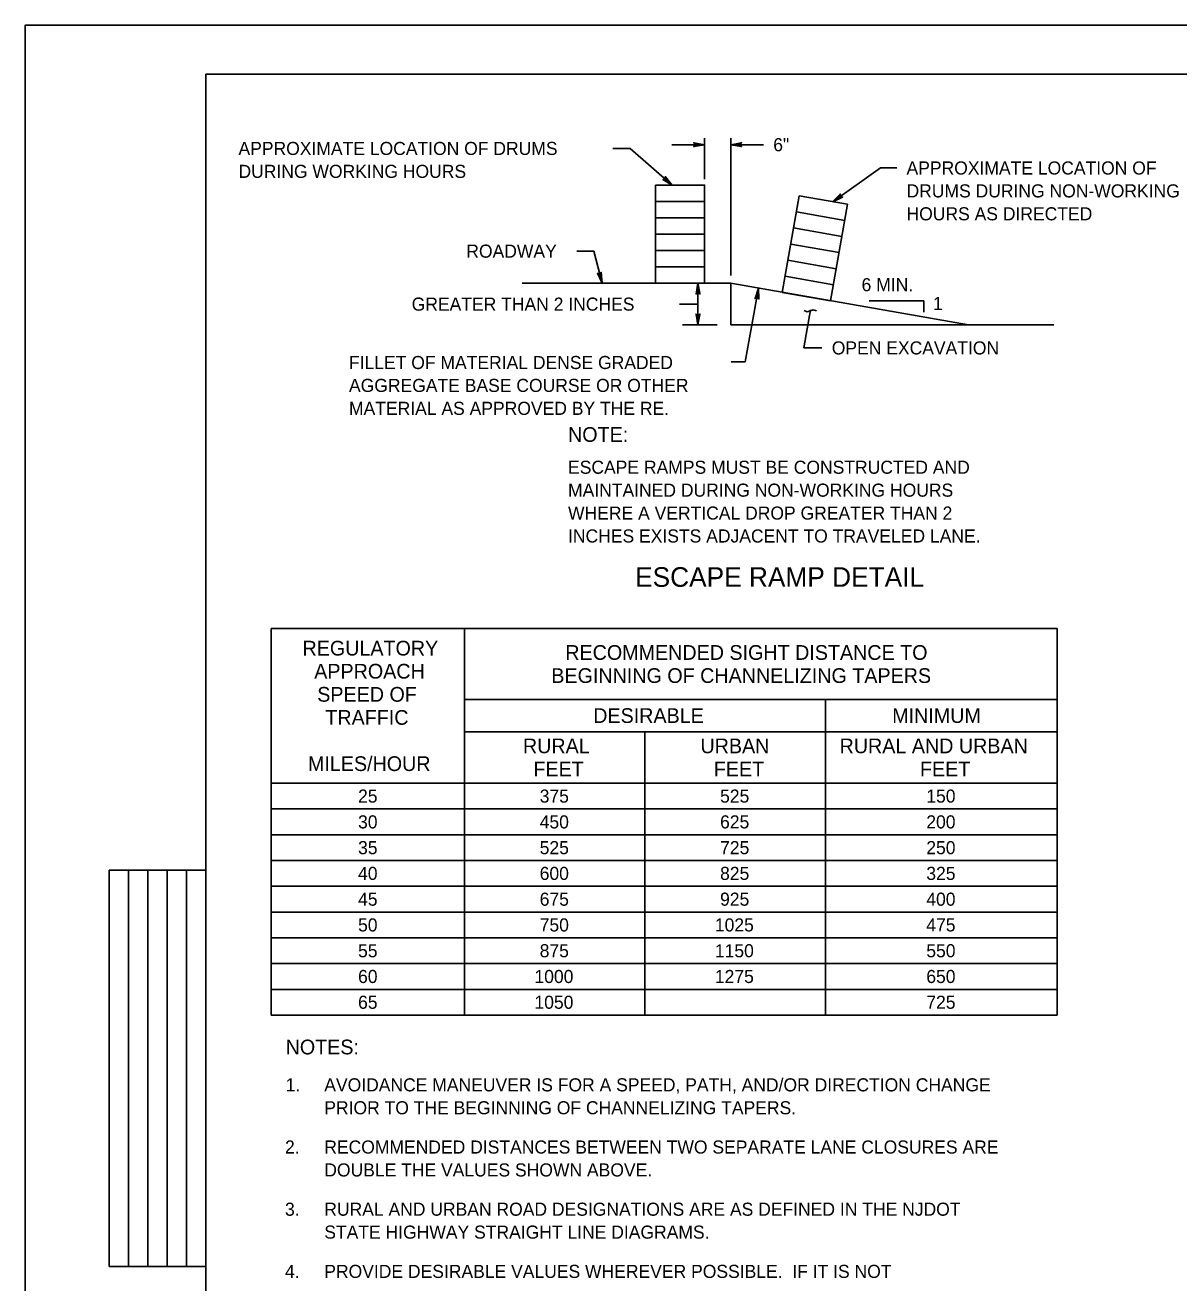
# Model space of a CAD drawing. Extents: x 499909 to 500993, y 502505 to 503165.
# Drawn here: x 499944.8 to 500297.3, y 502780.7 to 503165 of the extents above; entities that cross this region are included whole.
import ezdxf

# ---------------------------------------------------------------- set-up
doc = ezdxf.new("R2010")
doc.units = 0
for name, color, linetype in [('1', 7, 'Continuous'), ('24', 7, 'Continuous'), ('3', 7, 'Continuous'), ('39', 7, 'Continuous'), ('41', 7, 'Continuous'), ('5', 7, 'Continuous'), ('60', 7, 'Continuous')]:
    doc.layers.add(name, color=color, linetype=linetype)

msp = doc.modelspace()

# ---------------------------------------------------------------- linework, layer by layer
at = {"layer": '1'}
for p, q in [((500993, 503165), (499944.83, 503165)), ((500000, 503150), (500000, 502520)), ((500990, 503150), (500000, 503150)), ((499970.47, 502785.75), (499970.47, 502906.81)), ((499970.47, 502906.81), (500000, 502906.81)), ((499976.38, 502785.75), (499976.38, 502906.81)), ((499982.28, 502785.75), (499982.28, 502906.81)), ((499988.19, 502785.75), (499988.19, 502906.81)), ((499994.09, 502785.75), (499994.09, 502906.81)), ((500000, 502785.75), (499970.47, 502785.75))]:
    msp.add_line(p, q, dxfattribs=at)
at = {"layer": '24'}
for points in [[(500152.38, 503128.47), (500149.06, 503129.05), (500149.85, 503128.47), (500149.07, 503127.89), (500152.38, 503128.47), (500152.16, 503128.46), (500149.15, 503129.01), (500149.91, 503128.46), (500149.21, 503127.93), (500152.04, 503128.45), (500151.93, 503128.47), (500149.35, 503128.93), (500149.93, 503128.46), (500149.33, 503128.01), (500151.88, 503128.47), (500151.77, 503128.45), (500149.51, 503128.86), (500149.95, 503128.47), (500149.5, 503128.06), (500151.45, 503128.45), (500151.26, 503128.45), (500149.68, 503128.77), (500149.99, 503128.48), (500149.66, 503128.15), (500151.23, 503128.47), (500151.05, 503128.48), (500149.86, 503128.68), (500150.09, 503128.45), (500149.84, 503128.22), (500150.89, 503128.47), (500150.72, 503128.48), (500150.01, 503128.62), (500150.12, 503128.46), (500149.93, 503128.28), (500150.63, 503128.47), (500150.17, 503128.58), (500150.23, 503128.45), (500150.03, 503128.32), (500150.51, 503128.45), (500150.21, 503128.53), (500150.34, 503128.43), (500150.19, 503128.37), (500150.34, 503128.46), (500150.26, 503128.48)], [(500160.37, 503128.47), (500163.7, 503127.88), (500162.9, 503128.47), (500163.68, 503129.05), (500160.37, 503128.47), (500160.59, 503128.47), (500163.6, 503127.92), (500162.84, 503128.47), (500163.55, 503129), (500160.71, 503128.48), (500160.82, 503128.47), (500163.4, 503128.01), (500162.82, 503128.47), (500163.42, 503128.93), (500160.87, 503128.47), (500160.98, 503128.48), (500163.24, 503128.08), (500162.8, 503128.47), (500163.25, 503128.87), (500161.31, 503128.48), (500161.49, 503128.48), (500163.07, 503128.16), (500162.76, 503128.46), (500163.1, 503128.79), (500161.53, 503128.47), (500161.7, 503128.46), (500162.89, 503128.25), (500162.66, 503128.48), (500162.91, 503128.71), (500161.87, 503128.47), (500162.04, 503128.45), (500162.75, 503128.31), (500162.63, 503128.47), (500162.82, 503128.65), (500162.12, 503128.47), (500162.59, 503128.36), (500162.52, 503128.48), (500162.72, 503128.61), (500162.24, 503128.48), (500162.54, 503128.41), (500162.42, 503128.51), (500162.56, 503128.57), (500162.42, 503128.47), (500162.49, 503128.46)], [(500142.51, 503116.11), (500140.4, 503118.74), (500140.61, 503117.78), (500139.64, 503117.85), (500142.51, 503116.11), (500142.34, 503116.25), (500140.44, 503118.65), (500140.65, 503117.73), (500139.77, 503117.8), (500142.24, 503116.32), (500142.17, 503116.41), (500140.53, 503118.45), (500140.66, 503117.72), (500139.92, 503117.77), (500142.13, 503116.44), (500142.04, 503116.5), (500140.61, 503118.29), (500140.68, 503117.71), (500140.08, 503117.7), (500141.8, 503116.71), (500141.66, 503116.84), (500140.68, 503118.12), (500140.72, 503117.69), (500140.25, 503117.66), (500141.64, 503116.87), (500141.51, 503116.99), (500140.76, 503117.93), (500140.78, 503117.61), (500140.44, 503117.6), (500141.38, 503117.09), (500141.27, 503117.22), (500140.82, 503117.79), (500140.81, 503117.59), (500140.54, 503117.59), (500141.19, 503117.26), (500140.92, 503117.65), (500140.88, 503117.51), (500140.65, 503117.55), (500141.09, 503117.33), (500140.92, 503117.58), (500140.95, 503117.42), (500140.8, 503117.48), (500140.97, 503117.45), (500140.92, 503117.51)], [(500191.56, 503111.06), (500194.57, 503112.49), (500193.59, 503112.51), (500193.89, 503113.41), (500191.56, 503111.06), (500191.73, 503111.19), (500194.47, 503112.47), (500193.54, 503112.48), (500193.81, 503113.3), (500191.82, 503111.27), (500191.92, 503111.32), (500194.25, 503112.42), (500193.53, 503112.47), (500193.75, 503113.17), (500191.96, 503111.35), (500192.04, 503111.43), (500194.08, 503112.38), (500193.51, 503112.45), (500193.64, 503113.03), (500192.3, 503111.61), (500192.45, 503111.72), (500193.9, 503112.36), (500193.49, 503112.42), (500193.56, 503112.87), (500192.49, 503111.72), (500192.64, 503111.81), (500193.7, 503112.33), (500193.39, 503112.38), (500193.46, 503112.71), (500192.76, 503111.92), (500192.9, 503112), (500193.55, 503112.29), (500193.37, 503112.36), (500193.42, 503112.61), (500192.96, 503112.06), (500193.4, 503112.24), (500193.27, 503112.3), (500193.37, 503112.52), (500193.05, 503112.14), (500193.34, 503112.25), (500193.18, 503112.26), (500193.26, 503112.39), (500193.2, 503112.23), (500193.27, 503112.26)], [(500121.12, 503086.13), (500120.85, 503089.5), (500120.48, 503088.58), (500119.73, 503089.19), (500121.12, 503086.13), (500121.06, 503086.34), (500120.83, 503089.4), (500120.49, 503088.52), (500119.81, 503089.07), (500121.02, 503086.46), (500121.01, 503086.57), (500120.8, 503089.18), (500120.5, 503088.5), (500119.91, 503088.97), (500120.99, 503086.62), (500120.95, 503086.72), (500120.78, 503089), (500120.51, 503088.48), (500120, 503088.81), (500120.87, 503087.03), (500120.82, 503087.21), (500120.74, 503088.82), (500120.53, 503088.45), (500120.12, 503088.69), (500120.83, 503087.25), (500120.79, 503087.42), (500120.69, 503088.62), (500120.53, 503088.34), (500120.25, 503088.53), (500120.74, 503087.58), (500120.72, 503087.75), (500120.67, 503088.47), (500120.54, 503088.31), (500120.32, 503088.46), (500120.68, 503087.82), (500120.67, 503088.3), (500120.56, 503088.21), (500120.39, 503088.37), (500120.63, 503087.93), (500120.63, 503088.25), (500120.57, 503088.1), (500120.47, 503088.23), (500120.6, 503088.11), (500120.6, 503088.19)], [(500150.38, 503086.13), (500149.79, 503082.81), (500150.38, 503083.6), (500150.96, 503082.83), (500150.38, 503086.13), (500150.39, 503085.91), (500149.84, 503082.9), (500150.39, 503083.66), (500150.91, 503082.96), (500150.4, 503085.79), (500150.38, 503085.68), (500149.92, 503083.1), (500150.39, 503083.68), (500150.84, 503083.09), (500150.38, 503085.63), (500150.4, 503085.52), (500149.99, 503083.27), (500150.38, 503083.7), (500150.79, 503083.26), (500150.4, 503085.2), (500150.4, 503085.01), (500150.07, 503083.43), (500150.37, 503083.74), (500150.7, 503083.41), (500150.38, 503084.98), (500150.37, 503084.8), (500150.17, 503083.61), (500150.4, 503083.84), (500150.63, 503083.6), (500150.38, 503084.64), (500150.36, 503084.47), (500150.23, 503083.76), (500150.39, 503083.88), (500150.57, 503083.68), (500150.38, 503084.38), (500150.27, 503083.92), (500150.4, 503083.99), (500150.52, 503083.78), (500150.4, 503084.27), (500150.32, 503083.96), (500150.42, 503084.09), (500150.48, 503083.94), (500150.39, 503084.09), (500150.37, 503084.01)], [(500168.86, 503084.65), (500167.82, 503081.43), (500168.51, 503082.14), (500168.97, 503081.29), (500168.86, 503084.65), (500168.83, 503084.43), (500167.87, 503081.52), (500168.52, 503082.2), (500168.95, 503081.43), (500168.83, 503084.31), (500168.79, 503084.2), (500167.99, 503081.71), (500168.53, 503082.22), (500168.89, 503081.57), (500168.79, 503084.15), (500168.79, 503084.04), (500168.08, 503081.86), (500168.52, 503082.24), (500168.86, 503081.74), (500168.74, 503083.72), (500168.72, 503083.53), (500168.18, 503082.01), (500168.52, 503082.28), (500168.8, 503081.9), (500168.7, 503083.5), (500168.66, 503083.33), (500168.3, 503082.18), (500168.56, 503082.38), (500168.75, 503082.1), (500168.65, 503083.17), (500168.61, 503083), (500168.38, 503082.31), (500168.55, 503082.41), (500168.7, 503082.19), (500168.62, 503082.91), (500168.44, 503082.47), (500168.58, 503082.52), (500168.68, 503082.3), (500168.62, 503082.8), (500168.5, 503082.5), (500168.62, 503082.62), (500168.66, 503082.46), (500168.58, 503082.62), (500168.56, 503082.55)], [(500150.38, 503073.39), (500150.97, 503076.72), (500150.38, 503075.92), (500149.8, 503076.7), (500150.38, 503073.39), (500150.38, 503073.61), (500150.92, 503076.62), (500150.37, 503075.86), (500149.85, 503076.56), (500150.36, 503073.73), (500150.38, 503073.84), (500150.84, 503076.42), (500150.37, 503075.84), (500149.92, 503076.44), (500150.38, 503073.89), (500150.36, 503074), (500150.77, 503076.26), (500150.38, 503075.82), (500149.98, 503076.27), (500150.36, 503074.32), (500150.36, 503074.51), (500150.69, 503076.09), (500150.39, 503075.78), (500150.06, 503076.11), (500150.38, 503074.55), (500150.39, 503074.72), (500150.59, 503075.91), (500150.36, 503075.68), (500150.14, 503075.93), (500150.38, 503074.89), (500150.4, 503075.05), (500150.53, 503075.77), (500150.37, 503075.65), (500150.2, 503075.84), (500150.38, 503075.14), (500150.49, 503075.61), (500150.36, 503075.54), (500150.24, 503075.74), (500150.36, 503075.26), (500150.44, 503075.56), (500150.34, 503075.43), (500150.28, 503075.58), (500150.37, 503075.44), (500150.39, 503075.51)]]:
    msp.add_lwpolyline(points, dxfattribs=at)
at = {"layer": '3'}
for p, q in [((500137.39, 503086.13), (500137.39, 503116.11)), ((500137.39, 503116.11), (500152.38, 503116.11)), ((500152.38, 503086.13), (500152.38, 503116.11)), ((500176.1, 503083.35), (500181.31, 503112.87)), ((500181.31, 503112.87), (500196.07, 503110.27)), ((500137.39, 503111.11), (500152.38, 503111.11)), ((500190.86, 503080.75), (500196.07, 503110.27)), ((500137.39, 503106.12), (500152.38, 503106.12)), ((500180.44, 503107.95), (500195.2, 503105.35)), ((500179.57, 503103.03), (500194.33, 503100.43)), ((500137.39, 503101.12), (500152.38, 503101.12)), ((500178.7, 503098.11), (500193.47, 503095.51)), ((500137.39, 503096.12), (500152.38, 503096.12)), ((500137.39, 503091.13), (500152.38, 503091.13)), ((500177.84, 503093.19), (500192.6, 503090.59)), ((500160.37, 503086.13), (500096.67, 503086.13)), ((500137.39, 503086.13), (500152.38, 503086.13)), ((500150.38, 503086.13), (500150.38, 503073.39)), ((500160.37, 503073.39), (500160.37, 503086.13)), ((500160.37, 503086.13), (500233.07, 503073.39)), ((500176.97, 503088.27), (500191.73, 503085.67)), ((500176.1, 503083.35), (500190.86, 503080.75)), ((500150.38, 503079.76), (500144.77, 503079.76)), ((500156.23, 503073.39), (500145.69, 503073.39)), ((500160.37, 503073.39), (500259.14, 503073.39))]:
    msp.add_line(p, q, dxfattribs=at)
at = {"layer": '41'}
msp.add_lwpolyline([(499944.83, 502505), (500993, 502505), (500993, 503165), (499944.83, 503165)], close=True, dxfattribs=at)
at = {"layer": '5'}
for p, q in [((500152.38, 503128.47), (500142.39, 503128.47)), ((500152.38, 503117.96), (500152.38, 503130.47)), ((500160.37, 503088.49), (500160.37, 503130.47)), ((500160.37, 503128.47), (500170.37, 503128.47)), ((500124.36, 503127.34), (500129.69, 503127.34)), ((500129.69, 503127.34), (500142.51, 503116.11)), ((500206.09, 503121.36), (500191.56, 503111.06)), ((500211.09, 503121.36), (500206.09, 503121.36)), ((500113.35, 503095.95), (500118.57, 503095.95)), ((500118.57, 503095.95), (500121.12, 503086.13)), ((500164.8, 503062.1), (500168.86, 503084.65)), ((500202.64, 503080.73), (500219.35, 503080.73)), ((500219.35, 503080.73), (500219.35, 503077.34)), ((500184.73, 503078.06), (500182.74, 503066.38)), ((500182.74, 503066.38), (500188.25, 503066.38)), ((500164.8, 503062.1), (500160.48, 503062.1)), ((500020, 502980.62), (500020, 502862.51)), ((500020, 502980.62), (500260.16, 502980.62)), ((500079.05, 502980.62), (500079.05, 502862.51)), ((500260.16, 502980.62), (500260.16, 502862.51)), ((500079.05, 502958.96), (500260.16, 502958.96)), ((500189.29, 502958.96), (500189.29, 502862.51)), ((500079.05, 502949.12), (500260.16, 502949.12)), ((500134.17, 502949.12), (500134.17, 502862.51)), ((500020, 502933.37), (500260.16, 502933.37)), ((500020, 502925.5), (500260.16, 502925.5)), ((500020, 502917.63), (500260.16, 502917.63)), ((500020, 502909.75), (500260.16, 502909.75)), ((500020, 502901.88), (500260.16, 502901.88)), ((500020, 502894), (500260.16, 502894)), ((500020, 502886.13), (500260.16, 502886.13)), ((500020, 502878.26), (500260.16, 502878.26)), ((500020, 502870.38), (500260.16, 502870.38)), ((500020, 502862.51), (500260.16, 502862.51))]:
    msp.add_line(p, q, dxfattribs=at)
msp.add_lwpolyline([(500182.77, 503077.77), (500183.75, 503077.38), (500185.59, 503078.06), (500186.56, 503077.67)], dxfattribs=at)
at = {"layer": '60'}
for points in [[(500137.39, 503116.11), (500137.39, 503111.11), (500152.38, 503111.11), (500152.38, 503116.11)], [(500137.39, 503106.12), (500137.39, 503101.12), (500152.38, 503101.12), (500152.38, 503106.12)], [(500137.39, 503096.12), (500137.39, 503091.13), (500152.38, 503091.13), (500152.38, 503096.12)]]:
    msp.add_lwpolyline(points, close=True, dxfattribs=at)

# ---------------------------------------------------------------- texts
at = {"layer": '1'}
for s, height, p in [('APPROXIMATE LOCATION OF DRUMS ', 4, (500010, 503125.33)), ('DURING WORKING HOURS', 4, (500010, 503118.33)), ('APPROXIMATE LOCATION OF', 4, (500214.09, 503119.36)), ('DRUMS DURING NON-WORKING', 4, (500214.09, 503112.36)), ('HOURS AS DIRECTED', 4, (500214.09, 503105.36)), ('FILLET OF MATERIAL DENSE GRADED ', 4, (500043.76, 503059.92)), ('AGGREGATE BASE COURSE OR OTHER ', 4, (500043.76, 503052.92)), ('MATERIAL AS APPROVED BY THE RE.', 4, (500043.76, 503045.92)), ('ESCAPE RAMPS MUST BE CONSTRUCTED AND', 4, (500110.68, 503027.92)), ('MAINTAINED DURING NON-WORKING HOURS', 4, (500110.68, 503020.92)), ('WHERE A VERTICAL DROP GREATER THAN 2 ', 4, (500110.68, 503013.92)), ('INCHES EXISTS ADJACENT TO TRAVELED LANE.', 4, (500110.68, 503006.92)), (' ESCAPE RAMP DETAIL', 6, (500128.94, 502993.38)), ('1.', 4, (500024.4, 502839.21)), ('AVOIDANCE MANEUVER IS FOR A SPEED, PATH, AND/OR DIRECTION CHANGE', 4, (500036.21, 502839.21)), ('PRIOR TO THE BEGINNING OF CHANNELIZING TAPERS.', 4, (500036.21, 502832.21)), ('2.', 4, (500024.21, 502820.21)), ('RECOMMENDED DISTANCES BETWEEN TWO SEPARATE LANE CLOSURES ARE  ', 4, (500036.21, 502820.21)), ('DOUBLE THE VALUES SHOWN ABOVE.', 4, (500036.21, 502813.21)), ('3.', 4, (500024.21, 502801.21)), ('RURAL AND URBAN ROAD DESIGNATIONS ARE AS DEFINED IN THE NJDOT', 4, (500036.21, 502801.21)), ('STATE HIGHWAY STRAIGHT LINE DIAGRAMS.', 4, (500036.21, 502794.21)), ('4.', 4, (500024.21, 502782.21)), ('PROVIDE DESIRABLE VALUES WHEREVER POSSIBLE.  IF IT IS NOT', 4, (500036.21, 502782.21))]:
    msp.add_text(s, height=height, dxfattribs=at).set_placement(p)
at = {"layer": '39'}
for s, p in [('NOTE:', (500110.68, 503037.67)), ('REGULATORY', (500029.56, 502972.39)), (' RECOMMENDED SIGHT DISTANCE TO ', (500108.17, 502971.07)), ('APPROACH', (500033.14, 502965.34)), (' BEGINNING OF CHANNELIZING TAPERS', (500103.9, 502964.01)), ('SPEED OF', (500034.06, 502958.28)), ('TRAFFIC ', (500036.54, 502951.22)), ('DESIRABLE', (500118.38, 502951.79)), ('MINIMUM', (500209.72, 502951.79)), ('RURAL', (500096.9, 502942.53)), ('URBAN', (500151.14, 502942.53)), ('RURAL AND URBAN', (500193.64, 502942.53)), ('MILES/HOUR', (500031.23, 502937.1)), ('FEET', (500100.1, 502935.47)), ('FEET', (500155.22, 502935.47)), ('FEET', (500218.21, 502935.47)), ('NOTES:', (500024.4, 502850.52))]:
    msp.add_text(s, height=4.5, dxfattribs=at).set_placement(p)
at = {"layer": '5'}
for s, p in [('6"', (500173.37, 503126.47)), ('ROADWAY', (500079.6, 503093.95)), ('6 MIN.', (500200.36, 503083.7)), ('1', (500222.17, 503077.96)), ('GREATER THAN 2 INCHES', (500062.91, 503077.76)), ('OPEN EXCAVATION', (500191.25, 503064.38)), ('25', (500046.53, 502927.44)), ('375', (500102.02, 502927.44)), ('525', (500157.13, 502927.44)), ('150', (500220.13, 502927.44)), ('30', (500046.53, 502919.56)), ('450', (500102.02, 502919.56)), ('625', (500157.13, 502919.56)), ('200', (500220.13, 502919.56)), ('35', (500046.53, 502911.69)), ('525', (500102.02, 502911.69)), ('725', (500157.13, 502911.69)), ('250', (500220.13, 502911.69)), ('40', (500046.53, 502903.82)), ('600', (500102.02, 502903.82)), ('825', (500157.13, 502903.82)), ('325', (500220.13, 502903.82)), ('45', (500046.53, 502895.94)), ('675', (500102.02, 502895.94)), ('925', (500157.13, 502895.94)), ('400', (500220.13, 502895.94)), ('50', (500046.53, 502888.07)), ('750', (500102.02, 502888.07)), ('1025', (500155.54, 502888.07)), ('475', (500220.13, 502888.07)), ('55', (500046.53, 502880.19)), ('875', (500102.02, 502880.19)), ('1150', (500155.54, 502880.19)), ('550', (500220.13, 502880.19)), ('60', (500046.53, 502872.32)), ('1000', (500100.42, 502872.32)), ('1275', (500155.54, 502872.32)), ('650', (500220.13, 502872.32)), ('65', (500046.53, 502864.45)), ('1050', (500100.42, 502864.45)), ('725', (500220.13, 502864.45))]:
    msp.add_text(s, height=4, dxfattribs=at).set_placement(p)

doc.saveas('drawing.dxf')
